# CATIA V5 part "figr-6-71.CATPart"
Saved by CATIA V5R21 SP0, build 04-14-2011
Part number: Part2
Bounding box of the stored display mesh (mm): x -37.886 to 37.886, y -61.415 to 61.415, z 0 to 29
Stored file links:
  D:\CATIA V5R21 E-RESOURCES\CATIA-V5R21\catia-v5r21-prt\c06-catia-v5r21-prt\c06-catia-v5r21-figr-6-71.CATPart
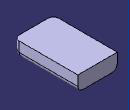
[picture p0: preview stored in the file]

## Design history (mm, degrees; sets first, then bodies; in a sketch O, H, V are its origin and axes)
Body1 (main body)
  Sketch1 on xy-plane, origin (0, 0, 0), H (1, 0, 0), V (0, 1, 0)
    line L1 (37.8862, 61.4155) -> (37.8862, -61.4155)
    line L2 (37.8862, -61.4155) -> (-37.8862, -61.4155)
    line L3 (-37.8862, -61.4155) -> (-37.8862, 61.4155)
    line L4 (-37.8862, 61.4155) -> (37.8862, 61.4155)
    vertical: L1 V, L3 V
    horizontal: L2 H, L4 H
    equidistance: L1 L3 O, L2 L4 O
  Pad1: profile Sketch1, direction (0, 0, 1), length 29
  Fillet1: radius 10, on edge [face of Pad1 | face of Pad1] (x5)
